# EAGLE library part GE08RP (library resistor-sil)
SIL RESISTOR
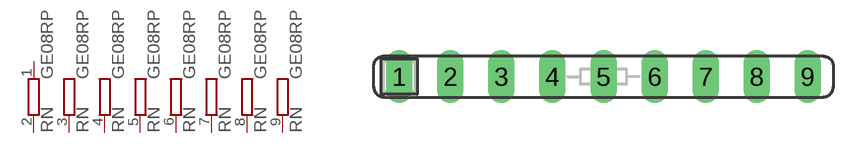
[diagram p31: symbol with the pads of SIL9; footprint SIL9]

Designator prefix RN; gates A=R-PV B=R-PV1 C=R-PV1 D=R-PV1 E=R-PV1 F=R-PV1 G=R-PV1 H=R-PV1

## GE08RP (OC_FARNELL: unknown; OC_NEWARK: unknown)  [SIL9]
1  A:1  pas
2  A:2  pas
3  B:2  pas
4  C:2  pas
5  D:2  pas
6  E:2  pas
7  F:2  pas
8  G:2  pas
9  H:2  pas

## Footprint SIL9 (pad centres in mm)
Single In Line
drill 0.813 long: 1 -10.16,0; 2 -7.62,0; 3 -5.08,0; 4 -2.54,0; 5 0,0; 6 2.54,0; 7 5.08,0; 8 7.62,0; 9 10.16,0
